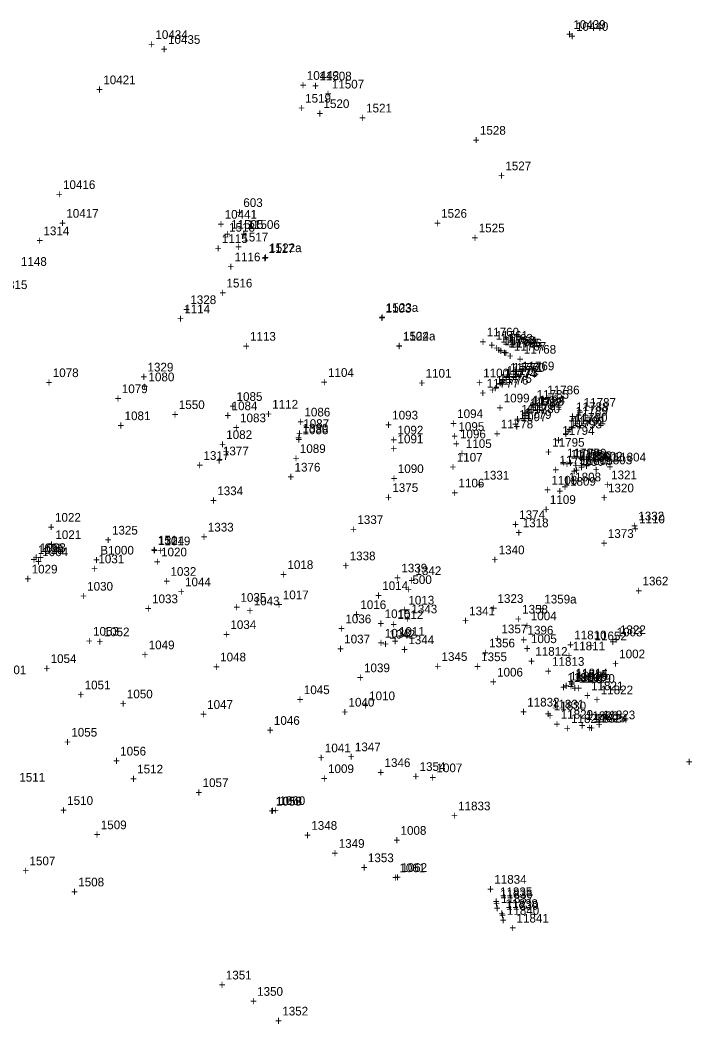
# Model space of a CAD drawing. Extents: x 1160051 to 1162814, y 614604 to 619560.
# Drawn here: x 1161430 to 1161623.3, y 617099.4 to 617388 of the extents above; entities that cross this region are included whole.
import ezdxf

# ---------------------------------------------------------------- set-up
doc = ezdxf.new("R2010")
doc.units = 0
for name, color, linetype in [('S_Control_Temp_Traverse', 7, 'Continuous'), ('S_Control_Traverse_Point', 7, 'Continuous'), ('S_Drainage_Culvert_Top', 7, 'Continuous'), ('S_Drainage_Ditch_Line', 7, 'Continuous'), ('S_Drainage_Invert', 7, 'Continuous'), ('S_Drainage_Waterway', 7, 'Continuous'), ('S_Fencing_Page', 7, 'Continuous'), ('S_Ground_Elevation', 7, 'Continuous'), ('S_Ground_SpotElevation', 7, 'Continuous'), ('S_Guardrail_Beam', 7, 'Continuous'), ('S_Roadway_Centerline', 7, 'Continuous'), ('S_Roadway_Edge_Pavement', 7, 'Continuous'), ('S_Roadway_Edge_Shoulder', 7, 'Continuous'), ('S_Trees_TreeLine', 7, 'Continuous'), ('S_Utilities_GuyWire3', 7, 'Continuous'), ('S_Utilities_Pole_Power', 7, 'Continuous'), ('S_Utilities_UG_BoringLocation', 7, 'Continuous'), ('S_Utilities_UG_Gas_Line', 7, 'Continuous'), ('S_Utilities_UG_Sanitary_Sewer', 7, 'Continuous')]:
    doc.layers.add(name, color=color, linetype=linetype)

msp = doc.modelspace()

# ---------------------------------------------------------------- texts
at = {"layer": 'S_Control_Temp_Traverse'}
for s, p in [('603', (1161494.24, 617334.26)), ('603', (1161494.24, 617334.26)), ('+', (1161492.18, 617331.51)), ('+', (1161492.18, 617331.51)), ('151', (1161469.67, 617237.22)), ('151', (1161469.67, 617237.22)), ('605', (1161437.03, 617235.01)), ('605', (1161437.03, 617235.01)), ('605', (1161437.03, 617235.01)), ('+', (1161467.61, 617234.47)), ('+', (1161467.61, 617234.47)), ('+', (1161434.97, 617232.26)), ('+', (1161434.97, 617232.26)), ('+', (1161434.97, 617232.26))]:
    msp.add_text(s, height=2.5, dxfattribs=at).set_placement(p)
at = {"layer": 'S_Control_Traverse_Point'}
for s, p in [('500', (1161542.87, 617225.87)), ('500', (1161542.87, 617225.87)), ('500', (1161542.87, 617225.87)), ('500', (1161542.87, 617225.87)), ('500', (1161542.87, 617225.87)), ('500', (1161542.87, 617225.87)), ('500', (1161542.87, 617225.87)), ('500', (1161542.87, 617225.87)), ('+', (1161540.81, 617223.12)), ('+', (1161540.81, 617223.12)), ('+', (1161540.81, 617223.12)), ('+', (1161540.81, 617223.12)), ('+', (1161540.81, 617223.12)), ('+', (1161540.81, 617223.12)), ('+', (1161540.81, 617223.12)), ('+', (1161540.81, 617223.12))]:
    msp.add_text(s, height=2.5, dxfattribs=at).set_placement(p)
at = {"layer": 'S_Drainage_Culvert_Top'}
for s, p in [('10439', (1161589.16, 617385.45)), ('+', (1161587.1, 617382.7)), ('11807', (1161590.48, 617259.85)), ('+', (1161588.42, 617257.1)), ('11814', (1161589.8, 617199.03)), ('+', (1161587.74, 617196.28)), ('1060', (1161504.61, 617162.35)), ('+', (1161502.55, 617159.6)), ('1061', (1161539.14, 617143.02)), ('+', (1161537.08, 617140.27))]:
    msp.add_text(s, height=2.5, dxfattribs=at).set_placement(p)
at = {"layer": 'S_Drainage_Ditch_Line'}
for s, p in [('11764', (1161569.39, 617294.44)), ('+', (1161567.33, 617291.69)), ('11773', (1161569.66, 617285.4)), ('+', (1161567.6, 617282.65)), ('11782', (1161576.62, 617276.61)), ('+', (1161574.56, 617273.86)), ('11791', (1161589.23, 617271.8)), ('+', (1161587.17, 617269.05)), ('11800', (1161590.97, 617261.52)), ('+', (1161588.91, 617258.77)), ('11818', (1161589.56, 617197.98)), ('+', (1161587.5, 617195.23)), ('11827', (1161588.51, 617185.93)), ('+', (1161586.45, 617183.18)), ('11837', (1161568.33, 617134.2)), ('+', (1161566.27, 617131.45))]:
    msp.add_text(s, height=2.5, dxfattribs=at).set_placement(p)
at = {"layer": 'S_Drainage_Invert'}
for s, p in [('10440', (1161589.92, 617384.88)), ('+', (1161587.86, 617382.13)), ('11805', (1161591.17, 617260.11)), ('+', (1161589.11, 617257.36)), ('11815', (1161589.79, 617198.65)), ('+', (1161587.73, 617195.9)), ('1059', (1161503.55, 617162.16)), ('+', (1161501.49, 617159.41)), ('1062', (1161539.67, 617143.11)), ('+', (1161537.61, 617140.36))]:
    msp.add_text(s, height=2.5, dxfattribs=at).set_placement(p)
at = {"layer": 'S_Drainage_Waterway'}
for s, p in [('11762', (1161568.19, 617295.26)), ('+', (1161566.12, 617292.51)), ('11766', (1161570.83, 617293.84)), ('+', (1161568.77, 617291.09)), ('11771', (1161570.94, 617286.86)), ('11775', (1161567.92, 617283.7)), ('+', (1161568.88, 617284.11)), ('+', (1161565.86, 617280.95)), ('11784', (1161577.49, 617277.55)), ('+', (1161575.43, 617274.8)), ('11780', (1161576.04, 617274.99)), ('11789', (1161589.77, 617274.3)), ('+', (1161573.98, 617272.24)), ('+', (1161587.71, 617271.55)), ('11793', (1161588.1, 617270.6)), ('+', (1161586.04, 617267.85)), ('11798', (1161588.42, 617261.93)), ('11802', (1161594.02, 617261.36)), ('+', (1161586.36, 617259.18)), ('+', (1161591.95, 617258.61)), ('11816', (1161587.42, 617197.74)), ('11820', (1161591.79, 617197.47)), ('+', (1161585.36, 617194.99)), ('+', (1161589.73, 617194.72)), ('11830', (1161583.53, 617189.56)), ('+', (1161581.47, 617186.81)), ('11825', (1161594.94, 617186.13)), ('+', (1161592.88, 617183.38)), ('11835', (1161568.05, 617136.13)), ('+', (1161565.99, 617133.38)), ('11839', (1161569.86, 617132.22)), ('+', (1161567.79, 617129.47))]:
    msp.add_text(s, height=2.5, dxfattribs=at).set_placement(p)
at = {"layer": 'S_Fencing_Page'}
for s, p in [('1116', (1161491.73, 617318.64)), ('+', (1161489.67, 617315.89)), ('1112', (1161502.56, 617276.29)), ('+', (1161500.5, 617273.54)), ('1105', (1161558.25, 617264.99)), ('+', (1161556.18, 617262.24)), ('1044', (1161477.48, 617225.21)), ('+', (1161475.42, 617222.46)), ('1043', (1161497.23, 617219.74)), ('+', (1161495.17, 617216.99)), ('1053', (1161451.02, 617211.02)), ('+', (1161448.96, 617208.27)), ('1042', (1161536.22, 617210.18)), ('+', (1161534.16, 617207.43))]:
    msp.add_text(s, height=2.5, dxfattribs=at).set_placement(p)
at = {"layer": 'S_Ground_Elevation'}
for s, p in [('10434', (1161468.96, 617382.55)), ('+', (1161466.9, 617379.8)), ('11508', (1161516.11, 617370.64)), ('+', (1161514.04, 617367.89)), ('11507', (1161519.7, 617368.32)), ('1519', (1161512.03, 617364.25)), ('+', (1161517.64, 617365.57)), ('+', (1161509.97, 617361.5)), ('1520', (1161517.31, 617362.69)), ('1521', (1161529.56, 617361.43)), ('+', (1161515.25, 617359.94)), ('+', (1161527.5, 617358.68)), ('1528', (1161562.29, 617355.03)), ('+', (1161560.22, 617352.28)), ('1527', (1161569.6, 617344.81)), ('+', (1161567.54, 617342.06)), ('10416', (1161442.39, 617339.42)), ('+', (1161440.33, 617336.67)), ('1526', (1161551.14, 617331.16)), ('1518', (1161490.16, 617327.17)), ('11505', (1161490.73, 617327.99)), ('11506', (1161495.46, 617327.95)), ('+', (1161549.07, 617328.41)), ('1525', (1161561.95, 617326.95)), ('+', (1161488.1, 617324.42)), ('1115', (1161488.07, 617323.9)), ('+', (1161488.67, 617325.24)), ('+', (1161493.4, 617325.2)), ('1517', (1161493.97, 617324.34)), ('+', (1161559.89, 617324.2)), ('+', (1161486.01, 617321.15)), ('+', (1161491.91, 617321.59)), ('1117', (1161501.5, 617321.07)), ('1522a', (1161501.71, 617321.27)), ('1148', (1161430.28, 617317.33)), ('+', (1161499.44, 617318.32)), ('+', (1161499.65, 617318.52)), ('1516', (1161489.4, 617311.12)), ('+', (1161487.34, 617308.37)), ('1114', (1161477.27, 617303.69)), ('1103', (1161535.15, 617303.87)), ('1523a', (1161535.26, 617304.09)), ('+', (1161475.21, 617300.94)), ('+', (1161533.09, 617301.12)), ('+', (1161533.2, 617301.34)), ('11760', (1161564.25, 617297.04)), ('1113', (1161496.17, 617295.81)), ('1102', (1161540.12, 617295.81)), ('1524a', (1161540.2, 617295.89)), ('11761', (1161566.82, 617296.09)), ('11763', (1161568.81, 617294.68)), ('+', (1161494.11, 617293.06)), ('+', (1161538.06, 617293.06)), ('+', (1161538.14, 617293.14)), ('+', (1161562.19, 617294.29)), ('+', (1161564.76, 617293.34)), ('+', (1161566.75, 617291.93)), ('11765', (1161570.44, 617293.93)), ('11767', (1161572.07, 617292.96)), ('11768', (1161574.92, 617292.08)), ('+', (1161568.38, 617291.18)), ('+', (1161570.01, 617290.21)), ('+', (1161572.86, 617289.33)), ('1078', (1161439.44, 617285.35)), ('1104', (1161518.61, 617285.41)), ('1100', (1161563.24, 617285.28)), ('11772', (1161570, 617286.04)), ('11770', (1161571.8, 617286.93)), ('11769', (1161574.4, 617287.31)), ('1080', (1161466.97, 617284.15)), ('1101', (1161546.67, 617285.19)), ('11776', (1161566.95, 617283.19)), ('+', (1161567.94, 617283.29)), ('11774', (1161569.2, 617285.09)), ('+', (1161569.74, 617284.18)), ('+', (1161572.34, 617284.56)), ('+', (1161437.38, 617282.6)), ('1079', (1161459.3, 617280.74)), ('+', (1161464.91, 617281.4)), ('+', (1161516.55, 617282.66)), ('+', (1161544.61, 617282.44)), ('+', (1161561.17, 617282.53)), ('11777', (1161564.22, 617282.33)), ('+', (1161564.89, 617280.44)), ('+', (1161567.14, 617282.34)), ('11786', (1161581.66, 617280.4)), ('+', (1161457.24, 617277.99)), ('1085', (1161492.3, 617278.51)), ('+', (1161562.16, 617279.58)), ('11783', (1161577.16, 617277.15)), ('11785', (1161578.62, 617279.12)), ('+', (1161579.6, 617277.65)), ('11787', (1161592.14, 617276.82)), ('+', (1161490.24, 617275.76)), ('1084', (1161490.87, 617275.83)), ('1086', (1161511.82, 617274.04)), ('+', (1161575.1, 617274.4)), ('+', (1161576.55, 617276.37)), ('11781', (1161576.6, 617275.85)), ('11788', (1161589.98, 617275.56)), ('+', (1161488.81, 617273.08)), ('1083', (1161493.31, 617272.37)), ('1093', (1161537.06, 617273.17)), ('1094', (1161555.75, 617273.57)), ('11779', (1161573.57, 617273.35)), ('+', (1161574.54, 617273.1)), ('+', (1161587.92, 617272.81)), ('11792', (1161588.75, 617271.31)), ('11790', (1161589.69, 617272.52)), ('+', (1161590.08, 617274.07)), ('+', (1161491.25, 617269.62)), ('+', (1161509.76, 617271.29)), ('1088', (1161511.28, 617268.94)), ('1087', (1161511.48, 617270.74)), ('+', (1161535, 617270.42)), ('1092', (1161538.58, 617268.87)), ('+', (1161553.69, 617270.82)), ('1095', (1161556.11, 617269.89)), ('11778', (1161568.3, 617270.61)), ('+', (1161571.51, 617270.6)), ('11794', (1161585.96, 617268.75)), ('+', (1161586.69, 617268.56)), ('+', (1161587.63, 617269.77)), ('+', (1161509.22, 617266.19)), ('+', (1161509.42, 617267.99)), ('+', (1161536.52, 617266.12)), ('1091', (1161538.59, 617266.32)), ('+', (1161554.05, 617267.14)), ('1096', (1161556.57, 617267.74)), ('+', (1161566.24, 617267.86)), ('11795', (1161583.08, 617265.35)), ('+', (1161583.9, 617266)), ('+', (1161536.53, 617263.57)), ('+', (1161554.51, 617264.99)), ('11797', (1161587.36, 617262.31)), ('11799', (1161589.41, 617262.25)), ('1107', (1161555.63, 617261.05)), ('+', (1161581.02, 617262.6)), ('11796', (1161585.18, 617260.25)), ('11801', (1161592.61, 617261)), ('11803', (1161596.79, 617260.27)), ('11804', (1161600.77, 617261.09)), ('+', (1161553.57, 617258.3)), ('+', (1161583.12, 617257.5)), ('+', (1161585.3, 617259.56)), ('+', (1161587.35, 617259.5)), ('+', (1161590.55, 617258.25)), ('+', (1161594.73, 617257.52)), ('+', (1161598.71, 617258.34)), ('1108', (1161582.85, 617254.46)), ('11809', (1161586.35, 617254.13)), ('11808', (1161587.83, 617255.37)), ('+', (1161580.79, 617251.71)), ('+', (1161584.29, 617251.38)), ('+', (1161585.77, 617252.62)), ('1021', (1161440.18, 617238.79)), ('1028', (1161435.11, 617234.48)), ('1064', (1161436.41, 617233.88)), ('+', (1161438.12, 617236.04)), ('1020', (1161470.59, 617233.82)), ('+', (1161433.05, 617231.73)), ('+', (1161434.35, 617231.13)), ('1031', (1161452.56, 617231.81)), ('+', (1161468.53, 617231.07)), ('1029', (1161433.37, 617228.9)), ('+', (1161450.5, 617229.06)), ('1032', (1161473.29, 617228.23)), ('+', (1161431.3, 617226.15)), ('+', (1161471.23, 617225.48)), ('1030', (1161449.33, 617223.96)), ('+', (1161447.27, 617221.21)), ('1033', (1161468, 617220.36)), ('1035', (1161493.42, 617220.76)), ('1017', (1161505.6, 617221.49)), ('+', (1161465.94, 617217.61)), ('+', (1161491.36, 617218.01)), ('+', (1161503.54, 617218.74)), ('1016', (1161527.9, 617218.67)), ('1015', (1161534.89, 617216.06)), ('1036', (1161523.6, 617214.59)), ('+', (1161525.84, 617215.92)), ('1012', (1161538.57, 617215.8)), ('1052', (1161454.07, 617210.85)), ('1034', (1161490.53, 617212.93)), ('+', (1161521.54, 617211.84)), ('+', (1161532.83, 617213.31)), ('1038', (1161534.93, 617210.48)), ('+', (1161536.51, 617213.05)), ('1011', (1161539, 617210.99)), ('+', (1161452.01, 617208.1)), ('+', (1161488.47, 617210.18)), ('1037', (1161523.26, 617208.79)), ('+', (1161536.94, 617208.24)), ('1005', (1161576.96, 617208.88)), ('11810', (1161589.42, 617209.96)), ('1049', (1161467.03, 617207.11)), ('+', (1161521.2, 617206.04)), ('+', (1161532.87, 617207.73)), ('+', (1161574.9, 617206.13)), ('11812', (1161578.21, 617205.24)), ('+', (1161587.35, 617207.21)), ('11811', (1161588.99, 617206.8)), ('1002', (1161602.35, 617204.52)), ('1054', (1161438.82, 617203.16)), ('+', (1161464.97, 617204.36)), ('1048', (1161487.58, 617203.62)), ('+', (1161576.15, 617202.49)), ('11813', (1161583.04, 617202.35)), ('+', (1161586.93, 617204.05)), ('1501', (1161424.4, 617199.94)), ('+', (1161436.76, 617200.41)), ('+', (1161485.52, 617200.87)), ('1039', (1161528.96, 617200.52)), ('1006', (1161567.23, 617199.27)), ('+', (1161580.98, 617199.6)), ('+', (1161600.29, 617201.77)), ('+', (1161526.9, 617197.78)), ('+', (1161565.17, 617196.52)), ('11817', (1161588.19, 617198.14)), ('11819', (1161590.68, 617197.5)), ('1051', (1161448.6, 617195.59)), ('1050', (1161460.75, 617193)), ('1045', (1161511.65, 617194.21)), ('+', (1161586.13, 617195.39)), ('+', (1161588.61, 617194.75)), ('11821', (1161594.27, 617195.34)), ('11822', (1161597.04, 617194.17)), ('+', (1161446.54, 617192.84)), ('+', (1161509.59, 617191.46)), ('1040', (1161524.5, 617190.63)), ('1010', (1161530.43, 617192.47)), ('11832', (1161575.9, 617190.65)), ('11831', (1161583, 617190.09)), ('+', (1161592.21, 617192.59)), ('+', (1161594.98, 617191.42)), ('+', (1161458.69, 617190.25)), ('1047', (1161483.84, 617189.98)), ('+', (1161522.44, 617187.88)), ('+', (1161528.36, 617189.72)), ('+', (1161573.84, 617187.9)), ('+', (1161481.78, 617187.23)), ('1046', (1161503.04, 617185.38)), ('+', (1161580.94, 617187.34)), ('11829', (1161585.54, 617187.15)), ('11826', (1161592.78, 617186.75)), ('11824', (1161595.49, 617186.02)), ('11823', (1161597.66, 617186.99)), ('1055', (1161444.77, 617182)), ('+', (1161500.98, 617182.63)), ('+', (1161583.48, 617184.4)), ('+', (1161590.72, 617184)), ('+', (1161593.43, 617183.27)), ('+', (1161595.6, 617184.24)), ('+', (1161442.71, 617179.25)), ('1056', (1161458.83, 617176.57)), ('1041', (1161517.7, 617177.49)), ('+', (1161456.77, 617173.82)), ('+', (1161515.64, 617174.74)), ('+', (1161621.48, 617173.52)), ('1512', (1161463.72, 617171.42)), ('1009', (1161518.61, 617171.52)), ('1007', (1161549.8, 617171.77)), ('1511', (1161429.81, 617169.06)), ('+', (1161461.66, 617168.67)), ('1057', (1161482.53, 617167.5)), ('+', (1161516.55, 617168.77)), ('+', (1161547.73, 617169.02)), ('+', (1161480.47, 617164.75)), ('1510', (1161443.59, 617162.37)), ('1058', (1161503.7, 617162.24)), ('+', (1161441.53, 617159.62)), ('+', (1161501.64, 617159.49)), ('11833', (1161556.02, 617160.81)), ('+', (1161553.96, 617158.06)), ('1509', (1161453.25, 617155.38)), ('1008', (1161539.46, 617153.77)), ('+', (1161451.19, 617152.63)), ('+', (1161537.4, 617151.02)), ('1507', (1161432.75, 617145.02)), ('+', (1161430.69, 617142.27)), ('1508', (1161446.77, 617138.95)), ('11834', (1161566.42, 617139.71)), ('+', (1161444.71, 617136.2)), ('+', (1161564.36, 617136.96)), ('11836', (1161568.14, 617135.53)), ('+', (1161566.08, 617132.78)), ('11838', (1161569.67, 617132.75)), ('+', (1161567.61, 617130)), ('11840', (1161570.05, 617130.77)), ('+', (1161567.99, 617128.02)), ('11841', (1161572.82, 617128.54)), ('+', (1161570.75, 617125.79))]:
    msp.add_text(s, height=2.5, dxfattribs=at).set_placement(p)
at = {"layer": 'S_Ground_SpotElevation'}
for s, p in [('1099', (1161569.13, 617278.07)), ('+', (1161567.07, 617275.32)), ('1098', (1161574.2, 617274.85)), ('+', (1161572.14, 617272.1)), ('1097', (1161574, 617272.67)), ('+', (1161571.93, 617269.92))]:
    msp.add_text(s, height=2.5, dxfattribs=at).set_placement(p)
at = {"layer": 'S_Guardrail_Beam'}
for s, p in [('10435', (1161472.58, 617381.14)), ('+', (1161470.52, 617378.39)), ('10442', (1161512.51, 617370.81)), ('+', (1161510.45, 617368.06)), ('10417', (1161443.34, 617331.17)), ('10441', (1161488.89, 617330.88)), ('+', (1161441.28, 617328.42)), ('+', (1161486.83, 617328.13))]:
    msp.add_text(s, height=2.5, dxfattribs=at).set_placement(p)
at = {"layer": 'S_Roadway_Centerline'}
for s, p in [('1334', (1161486.76, 617251.41)), ('+', (1161484.7, 617248.66)), ('1337', (1161527.05, 617243.12)), ('+', (1161524.99, 617240.37)), ('1340', (1161567.68, 617234.42)), ('+', (1161565.62, 617231.67)), ('1362', (1161609.05, 617225.47)), ('+', (1161606.99, 617222.72)), ('1341', (1161559.21, 617216.86)), ('+', (1161557.15, 617214.11)), ('1345', (1161551.25, 617203.76)), ('+', (1161549.18, 617201.01)), ('1346', (1161534.86, 617173.26)), ('+', (1161532.8, 617170.51)), ('1349', (1161521.68, 617150.03)), ('+', (1161519.62, 617147.28)), ('1350', (1161498.22, 617107.49)), ('+', (1161496.16, 617104.74))]:
    msp.add_text(s, height=2.5, dxfattribs=at).set_placement(p)
at = {"layer": 'S_Roadway_Edge_Pavement'}
for s, p in [('1377', (1161488.37, 617262.86)), ('+', (1161486.31, 617260.11)), ('1376', (1161508.98, 617258.2)), ('+', (1161506.92, 617255.45)), ('1375', (1161537.1, 617252.32)), ('+', (1161535.04, 617249.57)), ('1374', (1161573.59, 617244.55)), ('1333', (1161484.03, 617240.96)), ('+', (1161571.53, 617241.8)), ('1373', (1161599.08, 617239.13)), ('+', (1161481.97, 617238.21)), ('+', (1161597.02, 617236.38)), ('1338', (1161524.83, 617232.69)), ('+', (1161522.77, 617229.94)), ('1339', (1161539.7, 617229.2)), ('1342', (1161543.75, 617228.44)), ('+', (1161537.64, 617226.45)), ('+', (1161541.69, 617225.69)), ('1359a', (1161580.8, 617220.27)), ('1343', (1161542.58, 617217.43)), ('1358', (1161574.42, 617217.36)), ('+', (1161578.74, 617217.52)), ('+', (1161540.52, 617214.68)), ('+', (1161572.36, 617214.61)), ('1357', (1161568.48, 617211.71)), ('1344', (1161541.7, 617208.58)), ('1356', (1161564.94, 617207.65)), ('+', (1161566.42, 617208.96)), ('+', (1161539.64, 617205.83)), ('1355', (1161562.64, 617203.69)), ('+', (1161562.87, 617204.9)), ('+', (1161560.58, 617200.94)), ('1347', (1161526.33, 617177.79)), ('+', (1161524.27, 617175.04)), ('1354', (1161544.94, 617172.13)), ('+', (1161542.88, 617169.38)), ('1348', (1161513.8, 617155.21)), ('+', (1161511.74, 617152.46)), ('1353', (1161530.07, 617145.91)), ('+', (1161528.01, 617143.16)), ('1351', (1161489.21, 617112.19)), ('+', (1161487.15, 617109.44)), ('1352', (1161505.45, 617101.84)), ('+', (1161503.39, 617099.09))]:
    msp.add_text(s, height=2.5, dxfattribs=at).set_placement(p)
at = {"layer": 'S_Roadway_Edge_Shoulder'}
for s, p in [('1081', (1161460.09, 617272.97)), ('+', (1161458.02, 617270.22)), ('1082', (1161489.33, 617267.56)), ('+', (1161487.27, 617264.81)), ('1089', (1161510.5, 617263.54)), ('+', (1161508.44, 617260.79)), ('1090', (1161538.68, 617257.77)), ('+', (1161536.61, 617255.02)), ('1106', (1161556.13, 617253.64)), ('+', (1161554.07, 617250.89)), ('1109', (1161582.42, 617248.89)), ('+', (1161580.36, 617246.14)), ('1022', (1161440.08, 617243.78)), ('1110', (1161608.06, 617243.3)), ('+', (1161438.02, 617241.03)), ('+', (1161606, 617240.55)), ('1019', (1161471.57, 617237)), ('+', (1161469.51, 617234.25)), ('1018', (1161506.93, 617230.16)), ('+', (1161504.86, 617227.41)), ('1014', (1161534.2, 617224.13)), ('+', (1161532.14, 617221.38)), ('1013', (1161541.72, 617219.97)), ('+', (1161539.66, 617217.22)), ('1004', (1161576.92, 617215.45)), ('+', (1161574.86, 617212.7)), ('1003', (1161601.62, 617210.81)), ('11652', (1161595.26, 617209.7)), ('+', (1161599.56, 617208.06)), ('+', (1161593.19, 617206.95))]:
    msp.add_text(s, height=2.5, dxfattribs=at).set_placement(p)
at = {"layer": 'S_Trees_TreeLine'}
for s, p in [('10421', (1161453.97, 617369.55)), ('+', (1161451.91, 617366.8)), ('1314', (1161436.76, 617326.13)), ('+', (1161434.7, 617323.38)), ('1315', (1161424.71, 617310.66)), ('1328', (1161479.01, 617306.34)), ('+', (1161476.95, 617303.59)), ('1329', (1161466.69, 617286.96)), ('+', (1161464.63, 617284.21)), ('1330', (1161511.23, 617269.41)), ('+', (1161509.17, 617266.66)), ('1331', (1161563.3, 617255.9)), ('+', (1161561.24, 617253.15)), ('1332', (1161607.86, 617244.16)), ('+', (1161605.8, 617241.41)), ('1063', (1161435.73, 617235.08)), ('+', (1161433.67, 617232.33))]:
    msp.add_text(s, height=2.5, dxfattribs=at).set_placement(p)
at = {"layer": 'S_Utilities_GuyWire3'}
for s, p in [('1321', (1161600.02, 617255.98)), ('+', (1161597.96, 617253.23)), ('1325', (1161456.46, 617240.08)), ('+', (1161454.39, 617237.33))]:
    msp.add_text(s, height=2.5, dxfattribs=at).set_placement(p)
at = {"layer": 'S_Utilities_Pole_Power'}
for s, p in [('1320', (1161599.12, 617252.22)), ('+', (1161597.06, 617249.47)), ('1324', (1161469.82, 617237.05)), ('+', (1161467.76, 617234.3)), ('1396', (1161575.98, 617211.35)), ('+', (1161573.92, 617208.6))]:
    msp.add_text(s, height=2.5, dxfattribs=at).set_placement(p)
at = {"layer": 'S_Utilities_UG_BoringLocation'}
for s, p in [('1550', (1161475.7, 617276.16)), ('+', (1161473.64, 617273.41)), ('B1000', (1161453.09, 617234.33)), ('+', (1161451.03, 617231.58))]:
    msp.add_text(s, height=2.5, dxfattribs=at).set_placement(p)
at = {"layer": 'S_Utilities_UG_Gas_Line'}
for s, p in [('1317', (1161482.78, 617261.55)), ('+', (1161480.72, 617258.8)), ('1318', (1161574.6, 617242.19)), ('+', (1161572.53, 617239.44))]:
    msp.add_text(s, height=2.5, dxfattribs=at).set_placement(p)
at = {"layer": 'S_Utilities_UG_Sanitary_Sewer'}
for s, p in [('1323', (1161567.35, 617220.44)), ('+', (1161565.29, 617217.69)), ('1322', (1161602.57, 617211.47)), ('+', (1161600.51, 617208.72))]:
    msp.add_text(s, height=2.5, dxfattribs=at).set_placement(p)

doc.saveas('drawing.dxf')
